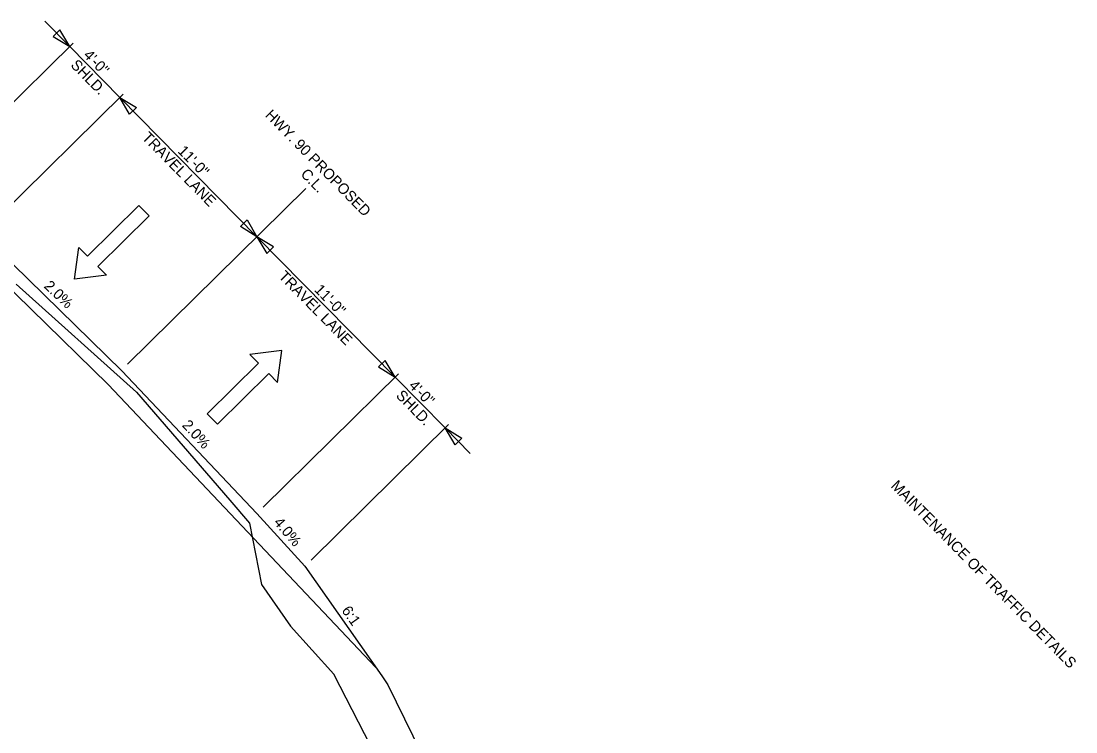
# Model space of a CAD drawing. Extents: x 1660305 to 1660468, y 670370 to 670550.
# Drawn here: x 1660408.5 to 1660467.6, y 670434.3 to 670474.1 of the extents above; entities that cross this region are included whole.
import ezdxf

# ---------------------------------------------------------------- set-up
doc = ezdxf.new("R2010")
doc.units = 0
for name, color, linetype in [('Default', 7, 'Continuous'), ('R_Annotation', 7, 'Continuous'), ('R_Border', 7, 'Continuous'), ('R_Dimension', 7, 'Continuous'), ('R_Exist Surface', 7, 'Continuous'), ('R_Horz Alg', 7, 'Continuous'), ('R_MOT', 7, 'Continuous')]:
    doc.layers.add(name, color=color, linetype=linetype)

msp = doc.modelspace()

# ---------------------------------------------------------------- linework, layer by layer
at = {"layer": 'Default'}
for points in [[(1660413.286, 670459.865), (1660411.497, 670459.647), (1660411.742, 670461.432), (1660412.225, 670460.943), (1660415.107, 670463.781), (1660415.686, 670463.193), (1660412.803, 670460.355)], [(1660422.869, 670453.864), (1660423.115, 670455.649), (1660421.325, 670455.431), (1660421.808, 670454.941), (1660418.925, 670452.103), (1660419.504, 670451.515), (1660422.387, 670454.354)]]:
    msp.add_lwpolyline(points, close=True, dxfattribs=at)
at = {"layer": 'R_Dimension'}
for p, q in [((1660411.229, 670472.686), (1660409.826, 670474.111)), ((1660403.71, 670465.283), (1660411.417, 670472.871)), ((1660414.035, 670469.836), (1660411.229, 670472.686)), ((1660406.631, 670462.545), (1660414.224, 670470.021)), ((1660414.035, 670469.836), (1660421.724, 670462.028)), ((1660429.471, 670454.16), (1660421.724, 670462.028)), ((1660422.067, 670446.869), (1660429.659, 670454.345)), ((1660429.471, 670454.16), (1660432.278, 670451.31)), ((1660424.759, 670443.907), (1660432.466, 670451.495)), ((1660432.278, 670451.31), (1660433.681, 670449.885))]:
    msp.add_line(p, q, dxfattribs=at)
for points in [[(1660410.3, 670473.253), (1660411.229, 670472.686), (1660410.676, 670473.624)], [(1660414.588, 670468.898), (1660414.035, 670469.836), (1660414.964, 670469.269)], [(1660421.171, 670462.966), (1660421.724, 670462.028), (1660420.795, 670462.595)], [(1660422.653, 670461.461), (1660421.724, 670462.028), (1660422.277, 670461.09)], [(1660428.542, 670454.727), (1660429.471, 670454.16), (1660428.918, 670455.098)], [(1660432.831, 670450.372), (1660432.278, 670451.31), (1660433.207, 670450.743)]]:
    msp.add_lwpolyline(points, close=True, dxfattribs=at)
at = {"layer": 'R_Exist Surface'}
msp.add_lwpolyline([(1660408.217, 670459.375), (1660414.98, 670453.311), (1660420.205, 670447.264), (1660421.314, 670445.969), (1660421.978, 670442.535), (1660423.615, 670440.2), (1660426.031, 670437.511), (1660426.036, 670437.482), (1660431.112, 670427.601)], dxfattribs=at)
at = {"layer": 'R_Horz Alg'}
msp.add_line((1660414.475, 670454.891), (1660424.467, 670464.73), dxfattribs=at)
at = {"layer": 'R_MOT'}
for points in [[(1660399.079, 670469.103), (1660403.354, 670464.932), (1660406.274, 670462.194), (1660414.149, 670454.51), (1660421.71, 670446.518), (1660424.403, 670443.556), (1660428.722, 670437.409), (1660429.066, 670436.92), (1660436.547, 670421.663)], [(1660400.41, 670466.403), (1660413.377, 670453.75), (1660428.39, 670437.882)]]:
    msp.add_lwpolyline(points, dxfattribs=at)

# ---------------------------------------------------------------- texts
at = {"layer": 'R_Annotation'}
for s, rotation, p in [('4\'-0"', 314.55764, (1660411.955, 670472.162)), ('SHLD.', 314.55764, (1660411.239, 670471.607)), ('HWY. 90 PROPOSED', 314.55764, (1660422.146, 670468.798)), ('TRAVEL LANE', 314.55764, (1660415.241, 670467.543)), ('11\'-0"', 314.55764, (1660417.246, 670466.789)), ('C.L.', 314.55764, (1660424.136, 670465.494)), ('TRAVEL LANE', 314.55764, (1660422.897, 670459.767)), ('2.0%', 316.55764, (1660409.744, 670459.208)), ('11\'-0"', 314.55764, (1660424.902, 670459.014)), ('4\'-0"', 314.55764, (1660430.198, 670453.636)), ('SHLD.', 314.55764, (1660429.482, 670453.081)), ('2.0%', 312.55764, (1660417.494, 670451.432)), ('4.0%', 310.55764, (1660422.63, 670445.995)), ('6:1', 305.09532, (1660426.447, 670441.075))]:
    msp.add_text(s, height=0.6, rotation=rotation, dxfattribs=at).set_placement(p)
at = {"layer": 'R_Border'}
msp.add_text('MAINTENANCE OF TRAFFIC DETAILS', height=0.6, rotation=314.55764, dxfattribs=at).set_placement((1660457.236, 670448.018))

doc.saveas('drawing.dxf')
